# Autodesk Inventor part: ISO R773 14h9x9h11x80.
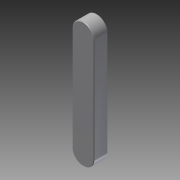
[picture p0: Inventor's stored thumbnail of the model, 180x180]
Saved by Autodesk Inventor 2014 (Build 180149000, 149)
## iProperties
Created: 2001-01
Part Number: ISO R773 14h9x9h11x80.
Material: Steel, Mild
Description: Key 14h9x9h11x80 ISO R773-A.
Document SubType Name: Modeling
Standard: ISO R773
Density: 7.86 g/cm^3
Appearance: Steel
ProtocolID: P00020918113032224
Protocol: P00020918113032224<@PID>[Version]<@EL>Version=2.2<@EL>[Synchronize]<@EL>ChangedVars=<@EL>[Calc]<@EL>ScnVisible=0<@EL>WizardMode=2<@EL>Optim=1<@EL>CalcName=KEY<@
Control State: 0
Master: False
Checked Out: False
Shininess: 20.0
Length Units: 11269
Angle Units: 11279
Time Units: 11290
Mass Units: 11283
Length Display Precision: 3
Angle Display Precision: 2
BOM1: Key Form A
BOM2: 14h9x9h11x80
BOM3: ISO R773
Density: 7.86
Volumn: 6.598322712661924
Area: 23.227147879536034
PropertySet Name: Model Information
Author: PaulN
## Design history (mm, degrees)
node "WorkPlane2"
sketch "Sketch2"
  geometry: L1 (-7, 7)-(-7, 73); L2 (7, 7)-(7, 73); L3 (0, -16)-(0, 96) reference; L4 (-9.8, 0)-(9.8, 0) reference; A1 r 7 centre (0, 7) between (-7, 7) and (7, 7); A2 r 7 centre (0, 73) between (7, 73) and (-7, 73)
  constraints: 4 end point, 4 point on circle, 4 tangent, 2 centre point, 2 vertical
  dimensions: "d2" = 66 distance of L2.start L2.end (= -prf_b + prf_l); "d7" = 7 distance between parallel lines of L3 L1 (= 0.5 x prf_b); "d8" = 14 distance between parallel lines of L2 L1 (= prf_b); "d9" = 7 distance from line of A1.centre L4 (= 0.5 x prf_b)
extrude "ExtrusionBlind1" new body sketch "Sketch2" distance "d3" = 9 (= prf_h); taper "d4" = 0 deg
chamfer "Chamfer2" distance "d14" = 0.4 (= prf_r); stored, may be unused: second distance "d15" = 0.4 (= prf_r), angle "d19" = 45 deg
body "Solid1"
other parameters: "prf_t1" = 5.5 [user parameter; used in 1 equation term], "prf_b" = 14 [user parameter; used in 4 equation terms], "prf_h" = 9 [user parameter; used in 1 equation term], "prf_l" = 80 [user parameter; used in 1 equation term], "prf_r" = 0.4 [user parameter; used in 2 equation terms], "d0" = -5.5 (computed from prf_t1), "d1" = 29 (derived), "msp_alfa" = 360 deg (computed from prf_pocper) [user parameter]
